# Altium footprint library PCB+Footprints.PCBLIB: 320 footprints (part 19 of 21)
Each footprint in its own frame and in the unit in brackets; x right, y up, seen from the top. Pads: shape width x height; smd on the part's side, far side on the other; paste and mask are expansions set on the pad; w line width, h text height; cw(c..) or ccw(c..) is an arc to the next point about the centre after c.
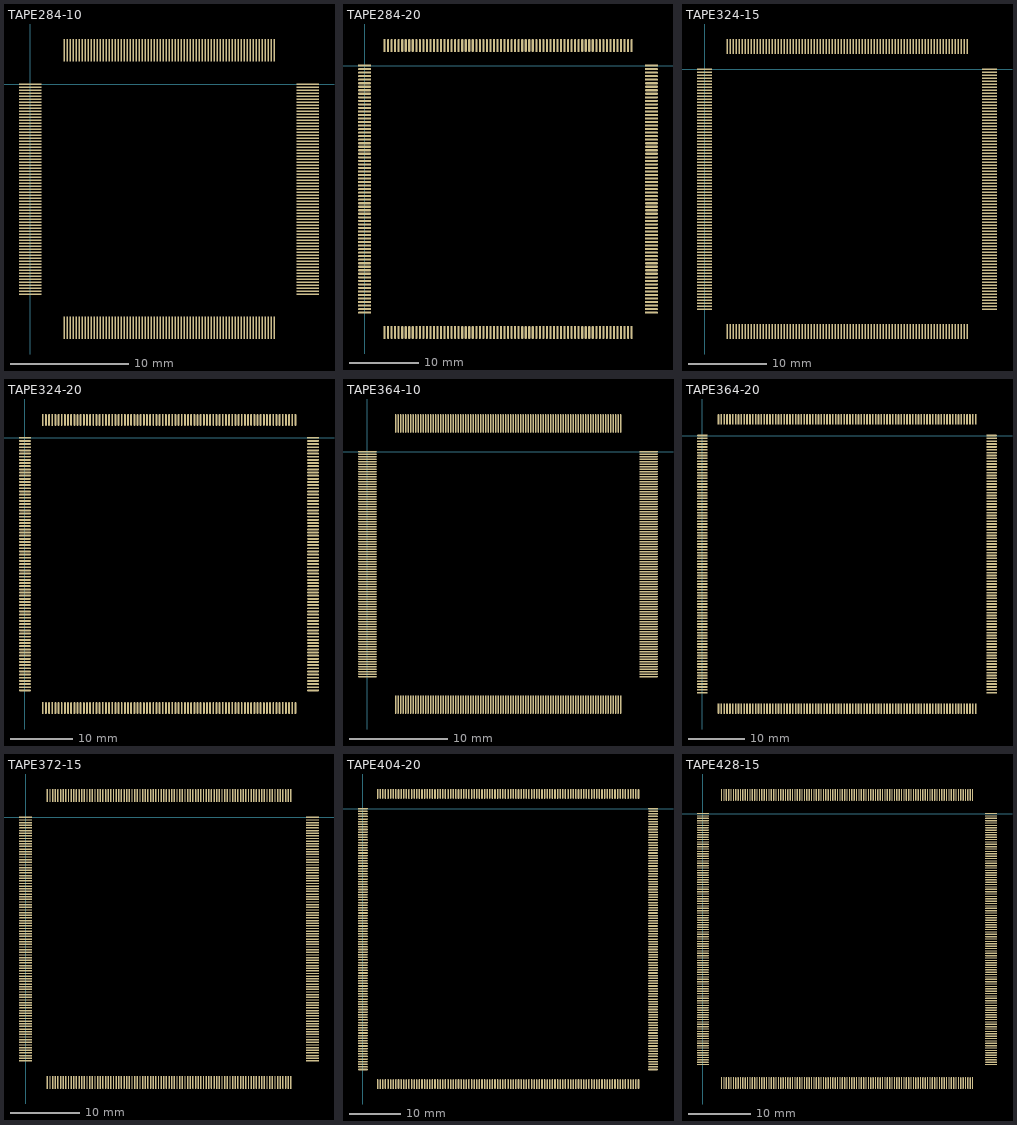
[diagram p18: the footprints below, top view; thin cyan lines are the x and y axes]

## TAPE284-10 [mil]
pads (284):
  oval 75x5 smd: 1(0,0) 2(0,-10) 3(0,-20) 4(0,-30) 5(0,-40) 6(0,-50) 7(0,-60) 8(0,-70) 9(0,-80) 10(0,-90) 11(0,-100) 12(0,-110) 13(0,-120) 14(0,-130) 15(0,-140) 16(0,-150) 17(0,-160) 18(0,-170) 19(0,-180) 20(0,-190) 21(0,-200) 22(0,-210) 23(0,-220) 24(0,-230) 25(0,-240) 26(0,-250) 27(0,-260) 28(0,-270) 29(0,-280) 30(0,-290) 31(0,-300) 32(0,-310) 33(0,-320) 34(0,-330) 35(0,-340) 36(0,-350) 37(0,-360) 38(0,-370) 39(0,-380) 40(0,-390) 41(0,-400) 42(0,-410) 43(0,-420) 44(0,-430) 45(0,-440) 46(0,-450) 47(0,-460) 48(0,-470) 49(0,-480) 50(0,-490) 51(0,-500) 52(0,-510) 53(0,-520) 54(0,-530) 55(0,-540) 56(0,-550) 57(0,-560) 58(0,-570) 59(0,-580) 60(0,-590) 61(0,-600) 62(0,-610) 63(0,-620) 64(0,-630) 65(0,-640) 66(0,-650) 67(0,-660) 68(0,-670) 69(0,-680) 70(0,-690) 71(0,-700) 143(925,-700) 144(925,-690) 145(925,-680) 146(925,-670) 147(925,-660) 148(925,-650) 149(925,-640) 150(925,-630) 151(925,-620) 152(925,-610) 153(925,-600) 154(925,-590) 155(925,-580) 156(925,-570) 157(925,-560) 158(925,-550) 159(925,-540) 160(925,-530) 161(925,-520) 162(925,-510) 163(925,-500) 164(925,-490) 165(925,-480) 166(925,-470) 167(925,-460) 168(925,-450) 169(925,-440) 170(925,-430) 171(925,-420) 172(925,-410) 173(925,-400) 174(925,-390) 175(925,-380) 176(925,-370) 177(925,-360) 178(925,-350) 179(925,-340) 180(925,-330) 181(925,-320) 182(925,-310) 183(925,-300) 184(925,-290) 185(925,-280) 186(925,-270) 187(925,-260) 188(925,-250) 189(925,-240) 190(925,-230) 191(925,-220) 192(925,-210) 193(925,-200) 194(925,-190) 195(925,-180) 196(925,-170) 197(925,-160) 198(925,-150) 199(925,-140) 200(925,-130) 201(925,-120) 202(925,-110) 203(925,-100) 204(925,-90) 205(925,-80) 206(925,-70) 207(925,-60) 208(925,-50) 209(925,-40) 210(925,-30) 211(925,-20) 212(925,-10) 213(925,0)
  oval 5x75 smd: 72(113,-812) 73(123,-812) 74(133,-812) 75(143,-812) 76(153,-812) 77(163,-812) 78(173,-812) 79(183,-812) 80(193,-812) 81(203,-812) 82(213,-812) 83(223,-812) 84(233,-812) 85(243,-812) 86(253,-812) 87(263,-812) 88(273,-812) 89(283,-812) 90(293,-812) 91(303,-812) 92(313,-812) 93(323,-812) 94(333,-812) 95(343,-812) 96(353,-812) 97(363,-812) 98(373,-812) 99(383,-812) 100(393,-812) 101(403,-812) 102(413,-812) 103(423,-812) 104(433,-812) 105(443,-812) 106(453,-812) 107(463,-812) 108(473,-812) 109(483,-812) 110(493,-812) 111(503,-812) 112(513,-812) 113(523,-812) 114(533,-812) 115(543,-812) 116(553,-812) 117(563,-812) 118(573,-812) 119(583,-812) 120(593,-812) 121(603,-812) 122(613,-812) 123(623,-812) 124(633,-812) 125(643,-812) 126(653,-812) 127(663,-812) 128(673,-812) 129(683,-812) 130(693,-812) 131(703,-812) 132(713,-812) 133(723,-812) 134(733,-812) 135(743,-812) 136(753,-812) 137(763,-812) 138(773,-812) 139(783,-812) 140(793,-812) 141(803,-812) 142(813,-812) 214(813,113) 215(803,113) 216(793,113) 217(783,113) 218(773,113) 219(763,113) 220(753,113) 221(743,113) 222(733,113) 223(723,113) 224(713,113) 225(703,113) 226(693,113) 227(683,113) 228(673,113) 229(663,113) 230(653,113) 231(643,113) 232(633,113) 233(623,113) 234(613,113) 235(603,113) 236(593,113) 237(583,113) 238(573,113) 239(563,113) 240(553,113) 241(543,113) 242(533,113) 243(523,113) 244(513,113) 245(503,113) 246(493,113) 247(483,113) 248(473,113) 249(463,113) 250(453,113) 251(443,113) 252(433,113) 253(423,113) 254(413,113) 255(403,113) 256(393,113) 257(383,113) 258(373,113) 259(363,113) 260(353,113) 261(343,113) 262(333,113) 263(323,113) 264(313,113) 265(303,113) 266(293,113) 267(283,113) 268(273,113) 269(263,113) 270(253,113) 271(243,113) 272(233,113) 273(223,113) 274(213,113) 275(203,113) 276(193,113) 277(183,113) 278(173,113) 279(163,113) 280(153,113) 281(143,113) 282(133,113) 283(123,113) 284(113,113)

## TAPE284-20 [mil]
pads (284):
  oval 75x12 smd: 1(0,0) 2(0,-20) 3(0,-40) 4(0,-60) 5(0,-80) 6(0,-100) 7(0,-120) 8(0,-140) 9(0,-160) 10(0,-180) 11(0,-200) 12(0,-220) 13(0,-240) 14(0,-260) 15(0,-280) 16(0,-300) 17(0,-320) 18(0,-340) 19(0,-360) 20(0,-380) 21(0,-400) 22(0,-420) 23(0,-440) 24(0,-460) 25(0,-480) 26(0,-500) 27(0,-520) 28(0,-540) 29(0,-560) 30(0,-580) 31(0,-600) 32(0,-620) 33(0,-640) 34(0,-660) 35(0,-680) 36(0,-700) 37(0,-720) 38(0,-740) 39(0,-760) 40(0,-780) 41(0,-800) 42(0,-820) 43(0,-840) 44(0,-860) 45(0,-880) 46(0,-900) 47(0,-920) 48(0,-940) 49(0,-960) 50(0,-980) 51(0,-1000) 52(0,-1020) 53(0,-1040) 54(0,-1060) 55(0,-1080) 56(0,-1100) 57(0,-1120) 58(0,-1140) 59(0,-1160) 60(0,-1180) 61(0,-1200) 62(0,-1220) 63(0,-1240) 64(0,-1260) 65(0,-1280) 66(0,-1300) 67(0,-1320) 68(0,-1340) 69(0,-1360) 70(0,-1380) 71(0,-1400) 143(1625,-1400) 144(1625,-1380) 145(1625,-1360) 146(1625,-1340) 147(1625,-1320) 148(1625,-1300) 149(1625,-1280) 150(1625,-1260) 151(1625,-1240) 152(1625,-1220) 153(1625,-1200) 154(1625,-1180) 155(1625,-1160) 156(1625,-1140) 157(1625,-1120) 158(1625,-1100) 159(1625,-1080) 160(1625,-1060) 161(1625,-1040) 162(1625,-1020) 163(1625,-1000) 164(1625,-980) 165(1625,-960) 166(1625,-940) 167(1625,-920) 168(1625,-900) 169(1625,-880) 170(1625,-860) 171(1625,-840) 172(1625,-820) 173(1625,-800) 174(1625,-780) 175(1625,-760) 176(1625,-740) 177(1625,-720) 178(1625,-700) 179(1625,-680) 180(1625,-660) 181(1625,-640) 182(1625,-620) 183(1625,-600) 184(1625,-580) 185(1625,-560) 186(1625,-540) 187(1625,-520) 188(1625,-500) 189(1625,-480) 190(1625,-460) 191(1625,-440) 192(1625,-420) 193(1625,-400) 194(1625,-380) 195(1625,-360) 196(1625,-340) 197(1625,-320) 198(1625,-300) 199(1625,-280) 200(1625,-260) 201(1625,-240) 202(1625,-220) 203(1625,-200) 204(1625,-180) 205(1625,-160) 206(1625,-140) 207(1625,-120) 208(1625,-100) 209(1625,-80) 210(1625,-60) 211(1625,-40) 212(1625,-20) 213(1625,0)
  oval 12x75 smd: 72(113,-1512) 73(133,-1512) 74(153,-1512) 75(173,-1512) 76(193,-1512) 77(213,-1512) 78(233,-1512) 79(253,-1512) 80(273,-1512) 81(293,-1512) 82(313,-1512) 83(333,-1512) 84(353,-1512) 85(373,-1512) 86(393,-1512) 87(413,-1512) 88(433,-1512) 89(453,-1512) 90(473,-1512) 91(493,-1512) 92(513,-1512) 93(533,-1512) 94(553,-1512) 95(573,-1512) 96(593,-1512) 97(613,-1512) 98(633,-1512) 99(653,-1512) 100(673,-1512) 101(693,-1512) 102(713,-1512) 103(733,-1512) 104(753,-1512) 105(773,-1512) 106(793,-1512) 107(813,-1512) 108(833,-1512) 109(853,-1512) 110(873,-1512) 111(893,-1512) 112(913,-1512) 113(933,-1512) 114(953,-1512) 115(973,-1512) 116(993,-1512) 117(1013,-1512) 118(1033,-1512) 119(1053,-1512) 120(1073,-1512) 121(1093,-1512) 122(1113,-1512) 123(1133,-1512) 124(1153,-1512) 125(1173,-1512) 126(1193,-1512) 127(1213,-1512) 128(1233,-1512) 129(1253,-1512) 130(1273,-1512) 131(1293,-1512) 132(1313,-1512) 133(1333,-1512) 134(1353,-1512) 135(1373,-1512) 136(1393,-1512) 137(1413,-1512) 138(1433,-1512) 139(1453,-1512) 140(1473,-1512) 141(1493,-1512) 142(1513,-1512) 214(1513,113) 215(1493,113) 216(1473,113) 217(1453,113) 218(1433,113) 219(1413,113) 220(1393,113) 221(1373,113) 222(1353,113) 223(1333,113) 224(1313,113) 225(1293,113) 226(1273,113) 227(1253,113) 228(1233,113) 229(1213,113) 230(1193,113) 231(1173,113) 232(1153,113) 233(1133,113) 234(1113,113) 235(1093,113) 236(1073,113) 237(1053,113) 238(1033,113) 239(1013,113) 240(993,113) 241(973,113) 242(953,113) 243(933,113) 244(913,113) 245(893,113) 246(873,113) 247(853,113) 248(833,113) 249(813,113) 250(793,113) 251(773,113) 252(753,113) 253(733,113) 254(713,113) 255(693,113) 256(673,113) 257(653,113) 258(633,113) 259(613,113) 260(593,113) 261(573,113) 262(553,113) 263(533,113) 264(513,113) 265(493,113) 266(473,113) 267(453,113) 268(433,113) 269(413,113) 270(393,113) 271(373,113) 272(353,113) 273(333,113) 274(313,113) 275(293,113) 276(273,113) 277(253,113) 278(233,113) 279(213,113) 280(193,113) 281(173,113) 282(153,113) 283(133,113) 284(113,113)

## TAPE324-15 [mil]
pads (324):
  oval 75x8 smd: 1(0,0) 2(0,-15) 3(0,-30) 4(0,-45) 5(0,-60) 6(0,-75) 7(0,-90) 8(0,-105) 9(0,-120) 10(0,-135) 11(0,-150) 12(0,-165) 13(0,-180) 14(0,-195) 15(0,-210) 16(0,-225) 17(0,-240) 18(0,-255) 19(0,-270) 20(0,-285) 21(0,-300) 22(0,-315) 23(0,-330) 24(0,-345) 25(0,-360) 26(0,-375) 27(0,-390) 28(0,-405) 29(0,-420) 30(0,-435) 31(0,-450) 32(0,-465) 33(0,-480) 34(0,-495) 35(0,-510) 36(0,-525) 37(0,-540) 38(0,-555) 39(0,-570) 40(0,-585) 41(0,-600) 42(0,-615) 43(0,-630) 44(0,-645) 45(0,-660) 46(0,-675) 47(0,-690) 48(0,-705) 49(0,-720) 50(0,-735) 51(0,-750) 52(0,-765) 53(0,-780) 54(0,-795) 55(0,-810) 56(0,-825) 57(0,-840) 58(0,-855) 59(0,-870) 60(0,-885) 61(0,-900) 62(0,-915) 63(0,-930) 64(0,-945) 65(0,-960) 66(0,-975) 67(0,-990) 68(0,-1005) 69(0,-1020) 70(0,-1035) 71(0,-1050) 72(0,-1065) 73(0,-1080) 74(0,-1095) 75(0,-1110) 76(0,-1125) 77(0,-1140) 78(0,-1155) 79(0,-1170) 80(0,-1185) 81(0,-1200) 163(1425,-1200) 164(1425,-1185) 165(1425,-1170) 166(1425,-1155) 167(1425,-1140) 168(1425,-1125) 169(1425,-1110) 170(1425,-1095) 171(1425,-1080) 172(1425,-1065) 173(1425,-1050) 174(1425,-1035) 175(1425,-1020) 176(1425,-1005) 177(1425,-990) 178(1425,-975) 179(1425,-960) 180(1425,-945) 181(1425,-930) 182(1425,-915) 183(1425,-900) 184(1425,-885) 185(1425,-870) 186(1425,-855) 187(1425,-840) 188(1425,-825) 189(1425,-810) 190(1425,-795) 191(1425,-780) 192(1425,-765) 193(1425,-750) 194(1425,-735) 195(1425,-720) 196(1425,-705) 197(1425,-690) 198(1425,-675) 199(1425,-660) 200(1425,-645) 201(1425,-630) 202(1425,-615) 203(1425,-600) 204(1425,-585) 205(1425,-570) 206(1425,-555) 207(1425,-540) 208(1425,-525) 209(1425,-510) 210(1425,-495) 211(1425,-480) 212(1425,-465) 213(1425,-450) 214(1425,-435) 215(1425,-420) 216(1425,-405) 217(1425,-390) 218(1425,-375) 219(1425,-360) 220(1425,-345) 221(1425,-330) 222(1425,-315) 223(1425,-300) 224(1425,-285) 225(1425,-270) 226(1425,-255) 227(1425,-240) 228(1425,-225) 229(1425,-210) 230(1425,-195) 231(1425,-180) 232(1425,-165) 233(1425,-150) 234(1425,-135) 235(1425,-120) 236(1425,-105) 237(1425,-90) 238(1425,-75) 239(1425,-60) 240(1425,-45) 241(1425,-30) 242(1425,-15) 243(1425,0)
  oval 8x75 smd: 82(113,-1312) 83(128,-1312) 84(143,-1312) 85(158,-1312) 86(173,-1312) 87(188,-1312) 88(203,-1312) 89(218,-1312) 90(233,-1312) 91(248,-1312) 92(263,-1312) 93(278,-1312) 94(293,-1312) 95(308,-1312) 96(323,-1312) 97(338,-1312) 98(353,-1312) 99(368,-1312) 100(383,-1312) 101(398,-1312) 102(413,-1312) 103(428,-1312) 104(443,-1312) 105(458,-1312) 106(473,-1312) 107(488,-1312) 108(503,-1312) 109(518,-1312) 110(533,-1312) 111(548,-1312) 112(563,-1312) 113(578,-1312) 114(593,-1312) 115(608,-1312) 116(623,-1312) 117(638,-1312) 118(653,-1312) 119(668,-1312) 120(683,-1312) 121(698,-1312) 122(713,-1312) 123(728,-1312) 124(743,-1312) 125(758,-1312) 126(773,-1312) 127(788,-1312) 128(803,-1312) 129(818,-1312) 130(833,-1312) 131(848,-1312) 132(863,-1312) 133(878,-1312) 134(893,-1312) 135(908,-1312) 136(923,-1312) 137(938,-1312) 138(953,-1312) 139(968,-1312) 140(983,-1312) 141(998,-1312) 142(1013,-1312) 143(1028,-1312) 144(1043,-1312) 145(1058,-1312) 146(1073,-1312) 147(1088,-1312) 148(1103,-1312) 149(1118,-1312) 150(1133,-1312) 151(1148,-1312) 152(1163,-1312) 153(1178,-1312) 154(1193,-1312) 155(1208,-1312) 156(1223,-1312) 157(1238,-1312) 158(1253,-1312) 159(1268,-1312) 160(1283,-1312) 161(1298,-1312) 162(1313,-1312) 244(1313,113) 245(1298,113) 246(1283,113) 247(1268,113) 248(1253,113) 249(1238,113) 250(1223,113) 251(1208,113) 252(1193,113) 253(1178,113) 254(1163,113) 255(1148,113) 256(1133,113) 257(1118,113) 258(1103,113) 259(1088,113) 260(1073,113) 261(1058,113) 262(1043,113) 263(1028,113) 264(1013,113) 265(998,113) 266(983,113) 267(968,113) 268(953,113) 269(938,113) 270(923,113) 271(908,113) 272(893,113) 273(878,113) 274(863,113) 275(848,113) 276(833,113) 277(818,113) 278(803,113) 279(788,113) 280(773,113) 281(758,113) 282(743,113) 283(728,113) 284(713,113) 285(698,113) 286(683,113) 287(668,113) 288(653,113) 289(638,113) 290(623,113) 291(608,113) 292(593,113) 293(578,113) 294(563,113) 295(548,113) 296(533,113) 297(518,113) 298(503,113) 299(488,113) 300(473,113) 301(458,113) 302(443,113) 303(428,113) 304(413,113) 305(398,113) 306(383,113) 307(368,113) 308(353,113) 309(338,113) 310(323,113) 311(308,113) 312(293,113) 313(278,113) 314(263,113) 315(248,113) 316(233,113) 317(218,113) 318(203,113) 319(188,113) 320(173,113) 321(158,113) 322(143,113) 323(128,113) 324(113,113)

## TAPE324-20 [mil]
pads (324):
  oval 75x12 smd: 1(0,0) 2(0,-20) 3(0,-40) 4(0,-60) 5(0,-80) 6(0,-100) 7(0,-120) 8(0,-140) 9(0,-160) 10(0,-180) 11(0,-200) 12(0,-220) 13(0,-240) 14(0,-260) 15(0,-280) 16(0,-300) 17(0,-320) 18(0,-340) 19(0,-360) 20(0,-380) 21(0,-400) 22(0,-420) 23(0,-440) 24(0,-460) 25(0,-480) 26(0,-500) 27(0,-520) 28(0,-540) 29(0,-560) 30(0,-580) 31(0,-600) 32(0,-620) 33(0,-640) 34(0,-660) 35(0,-680) 36(0,-700) 37(0,-720) 38(0,-740) 39(0,-760) 40(0,-780) 41(0,-800) 42(0,-820) 43(0,-840) 44(0,-860) 45(0,-880) 46(0,-900) 47(0,-920) 48(0,-940) 49(0,-960) 50(0,-980) 51(0,-1000) 52(0,-1020) 53(0,-1040) 54(0,-1060) 55(0,-1080) 56(0,-1100) 57(0,-1120) 58(0,-1140) 59(0,-1160) 60(0,-1180) 61(0,-1200) 62(0,-1220) 63(0,-1240) 64(0,-1260) 65(0,-1280) 66(0,-1300) 67(0,-1320) 68(0,-1340) 69(0,-1360) 70(0,-1380) 71(0,-1400) 72(0,-1420) 73(0,-1440) 74(0,-1460) 75(0,-1480) 76(0,-1500) 77(0,-1520) 78(0,-1540) 79(0,-1560) 80(0,-1580) 81(0,-1600) 163(1825,-1600) 164(1825,-1580) 165(1825,-1560) 166(1825,-1540) 167(1825,-1520) 168(1825,-1500) 169(1825,-1480) 170(1825,-1460) 171(1825,-1440) 172(1825,-1420) 173(1825,-1400) 174(1825,-1380) 175(1825,-1360) 176(1825,-1340) 177(1825,-1320) 178(1825,-1300) 179(1825,-1280) 180(1825,-1260) 181(1825,-1240) 182(1825,-1220) 183(1825,-1200) 184(1825,-1180) 185(1825,-1160) 186(1825,-1140) 187(1825,-1120) 188(1825,-1100) 189(1825,-1080) 190(1825,-1060) 191(1825,-1040) 192(1825,-1020) 193(1825,-1000) 194(1825,-980) 195(1825,-960) 196(1825,-940) 197(1825,-920) 198(1825,-900) 199(1825,-880) 200(1825,-860) 201(1825,-840) 202(1825,-820) 203(1825,-800) 204(1825,-780) 205(1825,-760) 206(1825,-740) 207(1825,-720) 208(1825,-700) 209(1825,-680) 210(1825,-660) 211(1825,-640) 212(1825,-620) 213(1825,-600) 214(1825,-580) 215(1825,-560) 216(1825,-540) 217(1825,-520) 218(1825,-500) 219(1825,-480) 220(1825,-460) 221(1825,-440) 222(1825,-420) 223(1825,-400) 224(1825,-380) 225(1825,-360) 226(1825,-340) 227(1825,-320) 228(1825,-300) 229(1825,-280) 230(1825,-260) 231(1825,-240) 232(1825,-220) 233(1825,-200) 234(1825,-180) 235(1825,-160) 236(1825,-140) 237(1825,-120) 238(1825,-100) 239(1825,-80) 240(1825,-60) 241(1825,-40) 242(1825,-20) 243(1825,0)
  oval 12x75 smd: 82(113,-1712) 83(133,-1712) 84(153,-1712) 85(173,-1712) 86(193,-1712) 87(213,-1712) 88(233,-1712) 89(253,-1712) 90(273,-1712) 91(293,-1712) 92(313,-1712) 93(333,-1712) 94(353,-1712) 95(373,-1712) 96(393,-1712) 97(413,-1712) 98(433,-1712) 99(453,-1712) 100(473,-1712) 101(493,-1712) 102(513,-1712) 103(533,-1712) 104(553,-1712) 105(573,-1712) 106(593,-1712) 107(613,-1712) 108(633,-1712) 109(653,-1712) 110(673,-1712) 111(693,-1712) 112(713,-1712) 113(733,-1712) 114(753,-1712) 115(773,-1712) 116(793,-1712) 117(813,-1712) 118(833,-1712) 119(853,-1712) 120(873,-1712) 121(893,-1712) 122(913,-1712) 123(933,-1712) 124(953,-1712) 125(973,-1712) 126(993,-1712) 127(1013,-1712) 128(1033,-1712) 129(1053,-1712) 130(1073,-1712) 131(1093,-1712) 132(1113,-1712) 133(1133,-1712) 134(1153,-1712) 135(1173,-1712) 136(1193,-1712) 137(1213,-1712) 138(1233,-1712) 139(1253,-1712) 140(1273,-1712) 141(1293,-1712) 142(1313,-1712) 143(1333,-1712) 144(1353,-1712) 145(1373,-1712) 146(1393,-1712) 147(1413,-1712) 148(1433,-1712) 149(1453,-1712) 150(1473,-1712) 151(1493,-1712) 152(1513,-1712) 153(1533,-1712) 154(1553,-1712) 155(1573,-1712) 156(1593,-1712) 157(1613,-1712) 158(1633,-1712) 159(1653,-1712) 160(1673,-1712) 161(1693,-1712) 162(1713,-1712) 244(1713,113) 245(1693,113) 246(1673,113) 247(1653,113) 248(1633,113) 249(1613,113) 250(1593,113) 251(1573,113) 252(1553,113) 253(1533,113) 254(1513,113) 255(1493,113) 256(1473,113) 257(1453,113) 258(1433,113) 259(1413,113) 260(1393,113) 261(1373,113) 262(1353,113) 263(1333,113) 264(1313,113) 265(1293,113) 266(1273,113) 267(1253,113) 268(1233,113) 269(1213,113) 270(1193,113) 271(1173,113) 272(1153,113) 273(1133,113) 274(1113,113) 275(1093,113) 276(1073,113) 277(1053,113) 278(1033,113) 279(1013,113) 280(993,113) 281(973,113) 282(953,113) 283(933,113) 284(913,113) 285(893,113) 286(873,113) 287(853,113) 288(833,113) 289(813,113) 290(793,113) 291(773,113) 292(753,113) 293(733,113) 294(713,113) 295(693,113) 296(673,113) 297(653,113) 298(633,113) 299(613,113) 300(593,113) 301(573,113) 302(553,113) 303(533,113) 304(513,113) 305(493,113) 306(473,113) 307(453,113) 308(433,113) 309(413,113) 310(393,113) 311(373,113) 312(353,113) 313(333,113) 314(313,113) 315(293,113) 316(273,113) 317(253,113) 318(233,113) 319(213,113) 320(193,113) 321(173,113) 322(153,113) 323(133,113) 324(113,113)

## TAPE364-10 [mil]
pads (364):
  oval 75x5 smd: 1(0,0) 2(0,-10) 3(0,-20) 4(0,-30) 5(0,-40) 6(0,-50) 7(0,-60) 8(0,-70) 9(0,-80) 10(0,-90) 11(0,-100) 12(0,-110) 13(0,-120) 14(0,-130) 15(0,-140) 16(0,-150) 17(0,-160) 18(0,-170) 19(0,-180) 20(0,-190) 21(0,-200) 22(0,-210) 23(0,-220) 24(0,-230) 25(0,-240) 26(0,-250) 27(0,-260) 28(0,-270) 29(0,-280) 30(0,-290) 31(0,-300) 32(0,-310) 33(0,-320) 34(0,-330) 35(0,-340) 36(0,-350) 37(0,-360) 38(0,-370) 39(0,-380) 40(0,-390) 41(0,-400) 42(0,-410) 43(0,-420) 44(0,-430) 45(0,-440) 46(0,-450) 47(0,-460) 48(0,-470) 49(0,-480) 50(0,-490) 51(0,-500) 52(0,-510) 53(0,-520) 54(0,-530) 55(0,-540) 56(0,-550) 57(0,-560) 58(0,-570) 59(0,-580) 60(0,-590) 61(0,-600) 62(0,-610) 63(0,-620) 64(0,-630) 65(0,-640) 66(0,-650) 67(0,-660) 68(0,-670) 69(0,-680) 70(0,-690) 71(0,-700) 72(0,-710) 73(0,-720) 74(0,-730) 75(0,-740) 76(0,-750) 77(0,-760) 78(0,-770) 79(0,-780) 80(0,-790) 81(0,-800) 82(0,-810) 83(0,-820) 84(0,-830) 85(0,-840) 86(0,-850) 87(0,-860) 88(0,-870) 89(0,-880) 90(0,-890) 91(0,-900) 183(1125,-900) 184(1125,-890) 185(1125,-880) 186(1125,-870) 187(1125,-860) 188(1125,-850) 189(1125,-840) 190(1125,-830) 191(1125,-820) 192(1125,-810) 193(1125,-800) 194(1125,-790) 195(1125,-780) 196(1125,-770) 197(1125,-760) 198(1125,-750) 199(1125,-740) 200(1125,-730) 201(1125,-720) 202(1125,-710) 203(1125,-700) 204(1125,-690) 205(1125,-680) 206(1125,-670) 207(1125,-660) 208(1125,-650) 209(1125,-640) 210(1125,-630) 211(1125,-620) 212(1125,-610) 213(1125,-600) 214(1125,-590) 215(1125,-580) 216(1125,-570) 217(1125,-560) 218(1125,-550) 219(1125,-540) 220(1125,-530) 221(1125,-520) 222(1125,-510) 223(1125,-500) 224(1125,-490) 225(1125,-480) 226(1125,-470) 227(1125,-460) 228(1125,-450) 229(1125,-440) 230(1125,-430) 231(1125,-420) 232(1125,-410) 233(1125,-400) 234(1125,-390) 235(1125,-380) 236(1125,-370) 237(1125,-360) 238(1125,-350) 239(1125,-340) 240(1125,-330) 241(1125,-320) 242(1125,-310) 243(1125,-300) 244(1125,-290) 245(1125,-280) 246(1125,-270) 247(1125,-260) 248(1125,-250) 249(1125,-240) 250(1125,-230) 251(1125,-220) 252(1125,-210) 253(1125,-200) 254(1125,-190) 255(1125,-180) 256(1125,-170) 257(1125,-160) 258(1125,-150) 259(1125,-140) 260(1125,-130) 261(1125,-120) 262(1125,-110) 263(1125,-100) 264(1125,-90) 265(1125,-80) 266(1125,-70) 267(1125,-60) 268(1125,-50) 269(1125,-40) 270(1125,-30) 271(1125,-20) 272(1125,-10) 273(1125,0)
  oval 5x75 smd: 92(113,-1012) 93(123,-1012) 94(133,-1012) 95(143,-1012) 96(153,-1012) 97(163,-1012) 98(173,-1012) 99(183,-1012) 100(193,-1012) 101(203,-1012) 102(213,-1012) 103(223,-1012) 104(233,-1012) 105(243,-1012) 106(253,-1012) 107(263,-1012) 108(273,-1012) 109(283,-1012) 110(293,-1012) 111(303,-1012) 112(313,-1012) 113(323,-1012) 114(333,-1012) 115(343,-1012) 116(353,-1012) 117(363,-1012) 118(373,-1012) 119(383,-1012) 120(393,-1012) 121(403,-1012) 122(413,-1012) 123(423,-1012) 124(433,-1012) 125(443,-1012) 126(453,-1012) 127(463,-1012) 128(473,-1012) 129(483,-1012) 130(493,-1012) 131(503,-1012) 132(513,-1012) 133(523,-1012) 134(533,-1012) 135(543,-1012) 136(553,-1012) 137(563,-1012) 138(573,-1012) 139(583,-1012) 140(593,-1012) 141(603,-1012) 142(613,-1012) 143(623,-1012) 144(633,-1012) 145(643,-1012) 146(653,-1012) 147(663,-1012) 148(673,-1012) 149(683,-1012) 150(693,-1012) 151(703,-1012) 152(713,-1012) 153(723,-1012) 154(733,-1012) 155(743,-1012) 156(753,-1012) 157(763,-1012) 158(773,-1012) 159(783,-1012) 160(793,-1012) 161(803,-1012) 162(813,-1012) 163(823,-1012) 164(833,-1012) 165(843,-1012) 166(853,-1012) 167(863,-1012) 168(873,-1012) 169(883,-1012) 170(893,-1012) 171(903,-1012) 172(913,-1012) 173(923,-1012) 174(933,-1012) 175(943,-1012) 176(953,-1012) 177(963,-1012) 178(973,-1012) 179(983,-1012) 180(993,-1012) 181(1003,-1012) 182(1013,-1012) 274(1013,113) 275(1003,113) 276(993,113) 277(983,113) 278(973,113) 279(963,113) 280(953,113) 281(943,113) 282(933,113) 283(923,113) 284(913,113) 285(903,113) 286(893,113) 287(883,113) 288(873,113) 289(863,113) 290(853,113) 291(843,113) 292(833,113) 293(823,113) 294(813,113) 295(803,113) 296(793,113) 297(783,113) 298(773,113) 299(763,113) 300(753,113) 301(743,113) 302(733,113) 303(723,113) 304(713,113) 305(703,113) 306(693,113) 307(683,113) 308(673,113) 309(663,113) 310(653,113) 311(643,113) 312(633,113) 313(623,113) 314(613,113) 315(603,113) 316(593,113) 317(583,113) 318(573,113) 319(563,113) 320(553,113) 321(543,113) 322(533,113) 323(523,113) 324(513,113) 325(503,113) 326(493,113) 327(483,113) 328(473,113) 329(463,113) 330(453,113) 331(443,113) 332(433,113) 333(423,113) 334(413,113) 335(403,113) 336(393,113) 337(383,113) 338(373,113) 339(363,113) 340(353,113) 341(343,113) 342(333,113) 343(323,113) 344(313,113) 345(303,113) 346(293,113) 347(283,113) 348(273,113) 349(263,113) 350(253,113) 351(243,113) 352(233,113) 353(223,113) 354(213,113) 355(203,113) 356(193,113) 357(183,113) 358(173,113) 359(163,113) 360(153,113) 361(143,113) 362(133,113) 363(123,113) 364(113,113)

## TAPE364-20 [mil]
pads (364):
  oval 75x12 smd: 1(0,0) 2(0,-20) 3(0,-40) 4(0,-60) 5(0,-80) 6(0,-100) 7(0,-120) 8(0,-140) 9(0,-160) 10(0,-180) 11(0,-200) 12(0,-220) 13(0,-240) 14(0,-260) 15(0,-280) 16(0,-300) 17(0,-320) 18(0,-340) 19(0,-360) 20(0,-380) 21(0,-400) 22(0,-420) 23(0,-440) 24(0,-460) 25(0,-480) 26(0,-500) 27(0,-520) 28(0,-540) 29(0,-560) 30(0,-580) 31(0,-600) 32(0,-620) 33(0,-640) 34(0,-660) 35(0,-680) 36(0,-700) 37(0,-720) 38(0,-740) 39(0,-760) 40(0,-780) 41(0,-800) 42(0,-820) 43(0,-840) 44(0,-860) 45(0,-880) 46(0,-900) 47(0,-920) 48(0,-940) 49(0,-960) 50(0,-980) 51(0,-1000) 52(0,-1020) 53(0,-1040) 54(0,-1060) 55(0,-1080) 56(0,-1100) 57(0,-1120) 58(0,-1140) 59(0,-1160) 60(0,-1180) 61(0,-1200) 62(0,-1220) 63(0,-1240) 64(0,-1260) 65(0,-1280) 66(0,-1300) 67(0,-1320) 68(0,-1340) 69(0,-1360) 70(0,-1380) 71(0,-1400) 72(0,-1420) 73(0,-1440) 74(0,-1460) 75(0,-1480) 76(0,-1500) 77(0,-1520) 78(0,-1540) 79(0,-1560) 80(0,-1580) 81(0,-1600) 82(0,-1620) 83(0,-1640) 84(0,-1660) 85(0,-1680) 86(0,-1700) 87(0,-1720) 88(0,-1740) 89(0,-1760) 90(0,-1780) 91(0,-1800) 183(2025,-1800) 184(2025,-1780) 185(2025,-1760) 186(2025,-1740) 187(2025,-1720) 188(2025,-1700) 189(2025,-1680) 190(2025,-1660) 191(2025,-1640) 192(2025,-1620) 193(2025,-1600) 194(2025,-1580) 195(2025,-1560) 196(2025,-1540) 197(2025,-1520) 198(2025,-1500) 199(2025,-1480) 200(2025,-1460) 201(2025,-1440) 202(2025,-1420) 203(2025,-1400) 204(2025,-1380) 205(2025,-1360) 206(2025,-1340) 207(2025,-1320) 208(2025,-1300) 209(2025,-1280) 210(2025,-1260) 211(2025,-1240) 212(2025,-1220) 213(2025,-1200) 214(2025,-1180) 215(2025,-1160) 216(2025,-1140) 217(2025,-1120) 218(2025,-1100) 219(2025,-1080) 220(2025,-1060) 221(2025,-1040) 222(2025,-1020) 223(2025,-1000) 224(2025,-980) 225(2025,-960) 226(2025,-940) 227(2025,-920) 228(2025,-900) 229(2025,-880) 230(2025,-860) 231(2025,-840) 232(2025,-820) 233(2025,-800) 234(2025,-780) 235(2025,-760) 236(2025,-740) 237(2025,-720) 238(2025,-700) 239(2025,-680) 240(2025,-660) 241(2025,-640) 242(2025,-620) 243(2025,-600) 244(2025,-580) 245(2025,-560) 246(2025,-540) 247(2025,-520) 248(2025,-500) 249(2025,-480) 250(2025,-460) 251(2025,-440) 252(2025,-420) 253(2025,-400) 254(2025,-380) 255(2025,-360) 256(2025,-340) 257(2025,-320) 258(2025,-300) 259(2025,-280) 260(2025,-260) 261(2025,-240) 262(2025,-220) 263(2025,-200) 264(2025,-180) 265(2025,-160) 266(2025,-140) 267(2025,-120) 268(2025,-100) 269(2025,-80) 270(2025,-60) 271(2025,-40) 272(2025,-20) 273(2025,0)
  oval 12x75 smd: 92(113,-1912) 93(133,-1912) 94(153,-1912) 95(173,-1912) 96(193,-1912) 97(213,-1912) 98(233,-1912) 99(253,-1912) 100(273,-1912) 101(293,-1912) 102(313,-1912) 103(333,-1912) 104(353,-1912) 105(373,-1912) 106(393,-1912) 107(413,-1912) 108(433,-1912) 109(453,-1912) 110(473,-1912) 111(493,-1912) 112(513,-1912) 113(533,-1912) 114(553,-1912) 115(573,-1912) 116(593,-1912) 117(613,-1912) 118(633,-1912) 119(653,-1912) 120(673,-1912) 121(693,-1912) 122(713,-1912) 123(733,-1912) 124(753,-1912) 125(773,-1912) 126(793,-1912) 127(813,-1912) 128(833,-1912) 129(853,-1912) 130(873,-1912) 131(893,-1912) 132(913,-1912) 133(933,-1912) 134(953,-1912) 135(973,-1912) 136(993,-1912) 137(1013,-1912) 138(1033,-1912) 139(1053,-1912) 140(1073,-1912) 141(1093,-1912) 142(1113,-1912) 143(1133,-1912) 144(1153,-1912) 145(1173,-1912) 146(1193,-1912) 147(1213,-1912) 148(1233,-1912) 149(1253,-1912) 150(1273,-1912) 151(1293,-1912) 152(1313,-1912) 153(1333,-1912) 154(1353,-1912) 155(1373,-1912) 156(1393,-1912) 157(1413,-1912) 158(1433,-1912) 159(1453,-1912) 160(1473,-1912) 161(1493,-1912) 162(1513,-1912) 163(1533,-1912) 164(1553,-1912) 165(1573,-1912) 166(1593,-1912) 167(1613,-1912) 168(1633,-1912) 169(1653,-1912) 170(1673,-1912) 171(1693,-1912) 172(1713,-1912) 173(1733,-1912) 174(1753,-1912) 175(1773,-1912) 176(1793,-1912) 177(1813,-1912) 178(1833,-1912) 179(1853,-1912) 180(1873,-1912) 181(1893,-1912) 182(1913,-1912) 274(1913,113) 275(1893,113) 276(1873,113) 277(1853,113) 278(1833,113) 279(1813,113) 280(1793,113) 281(1773,113) 282(1753,113) 283(1733,113) 284(1713,113) 285(1693,113) 286(1673,113) 287(1653,113) 288(1633,113) 289(1613,113) 290(1593,113) 291(1573,113) 292(1553,113) 293(1533,113) 294(1513,113) 295(1493,113) 296(1473,113) 297(1453,113) 298(1433,113) 299(1413,113) 300(1393,113) 301(1373,113) 302(1353,113) 303(1333,113) 304(1313,113) 305(1293,113) 306(1273,113) 307(1253,113) 308(1233,113) 309(1213,113) 310(1193,113) 311(1173,113) 312(1153,113) 313(1133,113) 314(1113,113) 315(1093,113) 316(1073,113) 317(1053,113) 318(1033,113) 319(1013,113) 320(993,113) 321(973,113) 322(953,113) 323(933,113) 324(913,113) 325(893,113) 326(873,113) 327(853,113) 328(833,113) 329(813,113) 330(793,113) 331(773,113) 332(753,113) 333(733,113) 334(713,113) 335(693,113) 336(673,113) 337(653,113) 338(633,113) 339(613,113) 340(593,113) 341(573,113) 342(553,113) 343(533,113) 344(513,113) 345(493,113) 346(473,113) 347(453,113) 348(433,113) 349(413,113) 350(393,113) 351(373,113) 352(353,113) 353(333,113) 354(313,113) 355(293,113) 356(273,113) 357(253,113) 358(233,113) 359(213,113) 360(193,113) 361(173,113) 362(153,113) 363(133,113) 364(113,113)

## TAPE372-15 [mil]
pads (372):
  oval 75x8 smd: 1(0,0) 2(0,-15) 3(0,-30) 4(0,-45) 5(0,-60) 6(0,-75) 7(0,-90) 8(0,-105) 9(0,-120) 10(0,-135) 11(0,-150) 12(0,-165) 13(0,-180) 14(0,-195) 15(0,-210) 16(0,-225) 17(0,-240) 18(0,-255) 19(0,-270) 20(0,-285) 21(0,-300) 22(0,-315) 23(0,-330) 24(0,-345) 25(0,-360) 26(0,-375) 27(0,-390) 28(0,-405) 29(0,-420) 30(0,-435) 31(0,-450) 32(0,-465) 33(0,-480) 34(0,-495) 35(0,-510) 36(0,-525) 37(0,-540) 38(0,-555) 39(0,-570) 40(0,-585) 41(0,-600) 42(0,-615) 43(0,-630) 44(0,-645) 45(0,-660) 46(0,-675) 47(0,-690) 48(0,-705) 49(0,-720) 50(0,-735) 51(0,-750) 52(0,-765) 53(0,-780) 54(0,-795) 55(0,-810) 56(0,-825) 57(0,-840) 58(0,-855) 59(0,-870) 60(0,-885) 61(0,-900) 62(0,-915) 63(0,-930) 64(0,-945) 65(0,-960) 66(0,-975) 67(0,-990) 68(0,-1005) 69(0,-1020) 70(0,-1035) 71(0,-1050) 72(0,-1065) 73(0,-1080) 74(0,-1095) 75(0,-1110) 76(0,-1125) 77(0,-1140) 78(0,-1155) 79(0,-1170) 80(0,-1185) 81(0,-1200) 82(0,-1215) 83(0,-1230) 84(0,-1245) 85(0,-1260) 86(0,-1275) 87(0,-1290) 88(0,-1305) 89(0,-1320) 90(0,-1335) 91(0,-1350) 92(0,-1365) 93(0,-1380) 187(1625,-1380) 188(1625,-1365) 189(1625,-1350) 190(1625,-1335) 191(1625,-1320) 192(1625,-1305) 193(1625,-1290) 194(1625,-1275) 195(1625,-1260) 196(1625,-1245) 197(1625,-1230) 198(1625,-1215) 199(1625,-1200) 200(1625,-1185) 201(1625,-1170) 202(1625,-1155) 203(1625,-1140) 204(1625,-1125) 205(1625,-1110) 206(1625,-1095) 207(1625,-1080) 208(1625,-1065) 209(1625,-1050) 210(1625,-1035) 211(1625,-1020) 212(1625,-1005) 213(1625,-990) 214(1625,-975) 215(1625,-960) 216(1625,-945) 217(1625,-930) 218(1625,-915) 219(1625,-900) 220(1625,-885) 221(1625,-870) 222(1625,-855) 223(1625,-840) 224(1625,-825) 225(1625,-810) 226(1625,-795) 227(1625,-780) 228(1625,-765) 229(1625,-750) 230(1625,-735) 231(1625,-720) 232(1625,-705) 233(1625,-690) 234(1625,-675) 235(1625,-660) 236(1625,-645) 237(1625,-630) 238(1625,-615) 239(1625,-600) 240(1625,-585) 241(1625,-570) 242(1625,-555) 243(1625,-540) 244(1625,-525) 245(1625,-510) 246(1625,-495) 247(1625,-480) 248(1625,-465) 249(1625,-450) 250(1625,-435) 251(1625,-420) 252(1625,-405) 253(1625,-390) 254(1625,-375) 255(1625,-360) 256(1625,-345) 257(1625,-330) 258(1625,-315) 259(1625,-300) 260(1625,-285) 261(1625,-270) 262(1625,-255) 263(1625,-240) 264(1625,-225) 265(1625,-210) 266(1625,-195) 267(1625,-180) 268(1625,-165) 269(1625,-150) 270(1625,-135) 271(1625,-120) 272(1625,-105) 273(1625,-90) 274(1625,-75) 275(1625,-60) 276(1625,-45) 277(1625,-30) 278(1625,-15) 279(1625,0)
  oval 8x75 smd: 94(123,-1502) 95(138,-1502) 96(153,-1502) 97(168,-1502) 98(183,-1502) 99(198,-1502) 100(213,-1502) 101(228,-1502) 102(243,-1502) 103(258,-1502) 104(273,-1502) 105(288,-1502) 106(303,-1502) 107(318,-1502) 108(333,-1502) 109(348,-1502) 110(363,-1502) 111(378,-1502) 112(393,-1502) 113(408,-1502) 114(423,-1502) 115(438,-1502) 116(453,-1502) 117(468,-1502) 118(483,-1502) 119(498,-1502) 120(513,-1502) 121(528,-1502) 122(543,-1502) 123(558,-1502) 124(573,-1502) 125(588,-1502) 126(603,-1502) 127(618,-1502) 128(633,-1502) 129(648,-1502) 130(663,-1502) 131(678,-1502) 132(693,-1502) 133(708,-1502) 134(723,-1502) 135(738,-1502) 136(753,-1502) 137(768,-1502) 138(783,-1502) 139(798,-1502) 140(813,-1502) 141(828,-1502) 142(843,-1502) 143(858,-1502) 144(873,-1502) 145(888,-1502) 146(903,-1502) 147(918,-1502) 148(933,-1502) 149(948,-1502) 150(963,-1502) 151(978,-1502) 152(993,-1502) 153(1008,-1502) 154(1023,-1502) 155(1038,-1502) 156(1053,-1502) 157(1068,-1502) 158(1083,-1502) 159(1098,-1502) 160(1113,-1502) 161(1128,-1502) 162(1143,-1502) 163(1158,-1502) 164(1173,-1502) 165(1188,-1502) 166(1203,-1502) 167(1218,-1502) 168(1233,-1502) 169(1248,-1502) 170(1263,-1502) 171(1278,-1502) 172(1293,-1502) 173(1308,-1502) 174(1323,-1502) 175(1338,-1502) 176(1353,-1502) 177(1368,-1502) 178(1383,-1502) 179(1398,-1502) 180(1413,-1502) 181(1428,-1502) 182(1443,-1502) 183(1458,-1502) 184(1473,-1502) 185(1488,-1502) 186(1503,-1502) 280(1503,123) 281(1488,123) 282(1473,123) 283(1458,123) 284(1443,123) 285(1428,123) 286(1413,123) 287(1398,123) 288(1383,123) 289(1368,123) 290(1353,123) 291(1338,123) 292(1323,123) 293(1308,123) 294(1293,123) 295(1278,123) 296(1263,123) 297(1248,123) 298(1233,123) 299(1218,123) 300(1203,123) 301(1188,123) 302(1173,123) 303(1158,123) 304(1143,123) 305(1128,123) 306(1113,123) 307(1098,123) 308(1083,123) 309(1068,123) 310(1053,123) 311(1038,123) 312(1023,123) 313(1008,123) 314(993,123) 315(978,123) 316(963,123) 317(948,123) 318(933,123) 319(918,123) 320(903,123) 321(888,123) 322(873,123) 323(858,123) 324(843,123) 325(828,123) 326(813,123) 327(798,123) 328(783,123) 329(768,123) 330(753,123) 331(738,123) 332(723,123) 333(708,123) 334(693,123) 335(678,123) 336(663,123) 337(648,123) 338(633,123) 339(618,123) 340(603,123) 341(588,123) 342(573,123) 343(558,123) 344(543,123) 345(528,123) 346(513,123) 347(498,123) 348(483,123) 349(468,123) 350(453,123) 351(438,123) 352(423,123) 353(408,123) 354(393,123) 355(378,123) 356(363,123) 357(348,123) 358(333,123) 359(318,123) 360(303,123) 361(288,123) 362(273,123) 363(258,123) 364(243,123) 365(228,123) 366(213,123) 367(198,123) 368(183,123) 369(168,123) 370(153,123) 371(138,123) 372(123,123)

## TAPE404-20 [mil]
pads (404):
  oval 75x12 smd: 1(0,0) 2(0,-20) 3(0,-40) 4(0,-60) 5(0,-80) 6(0,-100) 7(0,-120) 8(0,-140) 9(0,-160) 10(0,-180) 11(0,-200) 12(0,-220) 13(0,-240) 14(0,-260) 15(0,-280) 16(0,-300) 17(0,-320) 18(0,-340) 19(0,-360) 20(0,-380) 21(0,-400) 22(0,-420) 23(0,-440) 24(0,-460) 25(0,-480) 26(0,-500) 27(0,-520) 28(0,-540) 29(0,-560) 30(0,-580) 31(0,-600) 32(0,-620) 33(0,-640) 34(0,-660) 35(0,-680) 36(0,-700) 37(0,-720) 38(0,-740) 39(0,-760) 40(0,-780) 41(0,-800) 42(0,-820) 43(0,-840) 44(0,-860) 45(0,-880) 46(0,-900) 47(0,-920) 48(0,-940) 49(0,-960) 50(0,-980) 51(0,-1000) 52(0,-1020) 53(0,-1040) 54(0,-1060) 55(0,-1080) 56(0,-1100) 57(0,-1120) 58(0,-1140) 59(0,-1160) 60(0,-1180) 61(0,-1200) 62(0,-1220) 63(0,-1240) 64(0,-1260) 65(0,-1280) 66(0,-1300) 67(0,-1320) 68(0,-1340) 69(0,-1360) 70(0,-1380) 71(0,-1400) 72(0,-1420) 73(0,-1440) 74(0,-1460) 75(0,-1480) 76(0,-1500) 77(0,-1520) 78(0,-1540) 79(0,-1560) 80(0,-1580) 81(0,-1600) 82(0,-1620) 83(0,-1640) 84(0,-1660) 85(0,-1680) 86(0,-1700) 87(0,-1720) 88(0,-1740) 89(0,-1760) 90(0,-1780) 91(0,-1800) 92(0,-1820) 93(0,-1840) 94(0,-1860) 95(0,-1880) 96(0,-1900) 97(0,-1920) 98(0,-1940) 99(0,-1960) 100(0,-1980) 101(0,-2000) 203(2225,-2000) 204(2225,-1980) 205(2225,-1960) 206(2225,-1940) 207(2225,-1920) 208(2225,-1900) 209(2225,-1880) 210(2225,-1860) 211(2225,-1840) 212(2225,-1820) 213(2225,-1800) 214(2225,-1780) 215(2225,-1760) 216(2225,-1740) 217(2225,-1720) 218(2225,-1700) 219(2225,-1680) 220(2225,-1660) 221(2225,-1640) 222(2225,-1620) 223(2225,-1600) 224(2225,-1580) 225(2225,-1560) 226(2225,-1540) 227(2225,-1520) 228(2225,-1500) 229(2225,-1480) 230(2225,-1460) 231(2225,-1440) 232(2225,-1420) 233(2225,-1400) 234(2225,-1380) 235(2225,-1360) 236(2225,-1340) 237(2225,-1320) 238(2225,-1300) 239(2225,-1280) 240(2225,-1260) 241(2225,-1240) 242(2225,-1220) 243(2225,-1200) 244(2225,-1180) 245(2225,-1160) 246(2225,-1140) 247(2225,-1120) 248(2225,-1100) 249(2225,-1080) 250(2225,-1060) 251(2225,-1040) 252(2225,-1020) 253(2225,-1000) 254(2225,-980) 255(2225,-960) 256(2225,-940) 257(2225,-920) 258(2225,-900) 259(2225,-880) 260(2225,-860) 261(2225,-840) 262(2225,-820) 263(2225,-800) 264(2225,-780) 265(2225,-760) 266(2225,-740) 267(2225,-720) 268(2225,-700) 269(2225,-680) 270(2225,-660) 271(2225,-640) 272(2225,-620) 273(2225,-600) 274(2225,-580) 275(2225,-560) 276(2225,-540) 277(2225,-520) 278(2225,-500) 279(2225,-480) 280(2225,-460) 281(2225,-440) 282(2225,-420) 283(2225,-400) 284(2225,-380) 285(2225,-360) 286(2225,-340) 287(2225,-320) 288(2225,-300) 289(2225,-280) 290(2225,-260) 291(2225,-240) 292(2225,-220) 293(2225,-200) 294(2225,-180) 295(2225,-160) 296(2225,-140) 297(2225,-120) 298(2225,-100) 299(2225,-80) 300(2225,-60) 301(2225,-40) 302(2225,-20) 303(2225,0)
  oval 12x75 smd: 102(113,-2112) 103(133,-2112) 104(153,-2112) 105(173,-2112) 106(193,-2112) 107(213,-2112) 108(233,-2112) 109(253,-2112) 110(273,-2112) 111(293,-2112) 112(313,-2112) 113(333,-2112) 114(353,-2112) 115(373,-2112) 116(393,-2112) 117(413,-2112) 118(433,-2112) 119(453,-2112) 120(473,-2112) 121(493,-2112) 122(513,-2112) 123(533,-2112) 124(553,-2112) 125(573,-2112) 126(593,-2112) 127(613,-2112) 128(633,-2112) 129(653,-2112) 130(673,-2112) 131(693,-2112) 132(713,-2112) 133(733,-2112) 134(753,-2112) 135(773,-2112) 136(793,-2112) 137(813,-2112) 138(833,-2112) 139(853,-2112) 140(873,-2112) 141(893,-2112) 142(913,-2112) 143(933,-2112) 144(953,-2112) 145(973,-2112) 146(993,-2112) 147(1013,-2112) 148(1033,-2112) 149(1053,-2112) 150(1073,-2112) 151(1093,-2112) 152(1113,-2112) 153(1133,-2112) 154(1153,-2112) 155(1173,-2112) 156(1193,-2112) 157(1213,-2112) 158(1233,-2112) 159(1253,-2112) 160(1273,-2112) 161(1293,-2112) 162(1313,-2112) 163(1333,-2112) 164(1353,-2112) 165(1373,-2112) 166(1393,-2112) 167(1413,-2112) 168(1433,-2112) 169(1453,-2112) 170(1473,-2112) 171(1493,-2112) 172(1513,-2112) 173(1533,-2112) 174(1553,-2112) 175(1573,-2112) 176(1593,-2112) 177(1613,-2112) 178(1633,-2112) 179(1653,-2112) 180(1673,-2112) 181(1693,-2112) 182(1713,-2112) 183(1733,-2112) 184(1753,-2112) 185(1773,-2112) 186(1793,-2112) 187(1813,-2112) 188(1833,-2112) 189(1853,-2112) 190(1873,-2112) 191(1893,-2112) 192(1913,-2112) 193(1933,-2112) 194(1953,-2112) 195(1973,-2112) 196(1993,-2112) 197(2013,-2112) 198(2033,-2112) 199(2053,-2112) 200(2073,-2112) 201(2093,-2112) 202(2113,-2112) 304(2113,113) 305(2093,113) 306(2073,113) 307(2053,113) 308(2033,113) 309(2013,113) 310(1993,113) 311(1973,113) 312(1953,113) 313(1933,113) 314(1913,113) 315(1893,113) 316(1873,113) 317(1853,113) 318(1833,113) 319(1813,113) 320(1793,113) 321(1773,113) 322(1753,113) 323(1733,113) 324(1713,113) 325(1693,113) 326(1673,113) 327(1653,113) 328(1633,113) 329(1613,113) 330(1593,113) 331(1573,113) 332(1553,113) 333(1533,113) 334(1513,113) 335(1493,113) 336(1473,113) 337(1453,113) 338(1433,113) 339(1413,113) 340(1393,113) 341(1373,113) 342(1353,113) 343(1333,113) 344(1313,113) 345(1293,113) 346(1273,113) 347(1253,113) 348(1233,113) 349(1213,113) 350(1193,113) 351(1173,113) 352(1153,113) 353(1133,113) 354(1113,113) 355(1093,113) 356(1073,113) 357(1053,113) 358(1033,113) 359(1013,113) 360(993,113) 361(973,113) 362(953,113) 363(933,113) 364(913,113) 365(893,113) 366(873,113) 367(853,113) 368(833,113) 369(813,113) 370(793,113) 371(773,113) 372(753,113) 373(733,113) 374(713,113) 375(693,113) 376(673,113) 377(653,113) 378(633,113) 379(613,113) 380(593,113) 381(573,113) 382(553,113) 383(533,113) 384(513,113) 385(493,113) 386(473,113) 387(453,113) 388(433,113) 389(413,113) 390(393,113) 391(373,113) 392(353,113) 393(333,113) 394(313,113) 395(293,113) 396(273,113) 397(253,113) 398(233,113) 399(213,113) 400(193,113) 401(173,113) 402(153,113) 403(133,113) 404(113,113)

## TAPE428-15 [mil]
pads (428):
  oval 75x8 smd: 1(0,0) 2(0,-15) 3(0,-30) 4(0,-45) 5(0,-60) 6(0,-75) 7(0,-90) 8(0,-105) 9(0,-120) 10(0,-135) 11(0,-150) 12(0,-165) 13(0,-180) 14(0,-195) 15(0,-210) 16(0,-225) 17(0,-240) 18(0,-255) 19(0,-270) 20(0,-285) 21(0,-300) 22(0,-315) 23(0,-330) 24(0,-345) 25(0,-360) 26(0,-375) 27(0,-390) 28(0,-405) 29(0,-420) 30(0,-435) 31(0,-450) 32(0,-465) 33(0,-480) 34(0,-495) 35(0,-510) 36(0,-525) 37(0,-540) 38(0,-555) 39(0,-570) 40(0,-585) 41(0,-600) 42(0,-615) 43(0,-630) 44(0,-645) 45(0,-660) 46(0,-675) 47(0,-690) 48(0,-705) 49(0,-720) 50(0,-735) 51(0,-750) 52(0,-765) 53(0,-780) 54(0,-795) 55(0,-810) 56(0,-825) 57(0,-840) 58(0,-855) 59(0,-870) 60(0,-885) 61(0,-900) 62(0,-915) 63(0,-930) 64(0,-945) 65(0,-960) 66(0,-975) 67(0,-990) 68(0,-1005) 69(0,-1020) 70(0,-1035) 71(0,-1050) 72(0,-1065) 73(0,-1080) 74(0,-1095) 75(0,-1110) 76(0,-1125) 77(0,-1140) 78(0,-1155) 79(0,-1170) 80(0,-1185) 81(0,-1200) 82(0,-1215) 83(0,-1230) 84(0,-1245) 85(0,-1260) 86(0,-1275) 87(0,-1290) 88(0,-1305) 89(0,-1320) 90(0,-1335) 91(0,-1350) 92(0,-1365) 93(0,-1380) 94(0,-1395) 95(0,-1410) 96(0,-1425) 97(0,-1440) 98(0,-1455) 99(0,-1470) 100(0,-1485) 101(0,-1500) 102(0,-1515) 103(0,-1530) 104(0,-1545) 105(0,-1560) 106(0,-1575) 107(0,-1590) 215(1825,-1590) 216(1825,-1575) 217(1825,-1560) 218(1825,-1545) 219(1825,-1530) 220(1825,-1515) 221(1825,-1500) 222(1825,-1485) 223(1825,-1470) 224(1825,-1455) 225(1825,-1440) 226(1825,-1425) 227(1825,-1410) 228(1825,-1395) 229(1825,-1380) 230(1825,-1365) 231(1825,-1350) 232(1825,-1335) 233(1825,-1320) 234(1825,-1305) 235(1825,-1290) 236(1825,-1275) 237(1825,-1260) 238(1825,-1245) 239(1825,-1230) 240(1825,-1215) 241(1825,-1200) 242(1825,-1185) 243(1825,-1170) 244(1825,-1155) 245(1825,-1140) 246(1825,-1125) 247(1825,-1110) 248(1825,-1095) 249(1825,-1080) 250(1825,-1065) 251(1825,-1050) 252(1825,-1035) 253(1825,-1020) 254(1825,-1005) 255(1825,-990) 256(1825,-975) 257(1825,-960) 258(1825,-945) 259(1825,-930) 260(1825,-915) 261(1825,-900) 262(1825,-885) 263(1825,-870) 264(1825,-855) 265(1825,-840) 266(1825,-825) 267(1825,-810) 268(1825,-795) 269(1825,-780) 270(1825,-765) 271(1825,-750) 272(1825,-735) 273(1825,-720) 274(1825,-705) 275(1825,-690) 276(1825,-675) 277(1825,-660) 278(1825,-645) 279(1825,-630) 280(1825,-615) 281(1825,-600) 282(1825,-585) 283(1825,-570) 284(1825,-555) 285(1825,-540) 286(1825,-525) 287(1825,-510) 288(1825,-495) 289(1825,-480) 290(1825,-465) 291(1825,-450) 292(1825,-435) 293(1825,-420) 294(1825,-405) 295(1825,-390) 296(1825,-375) 297(1825,-360) 298(1825,-345) 299(1825,-330) 300(1825,-315) 301(1825,-300) 302(1825,-285) 303(1825,-270) 304(1825,-255) 305(1825,-240) 306(1825,-225) 307(1825,-210) 308(1825,-195) 309(1825,-180) 310(1825,-165) 311(1825,-150) 312(1825,-135) 313(1825,-120) 314(1825,-105) 315(1825,-90) 316(1825,-75) 317(1825,-60) 318(1825,-45) 319(1825,-30) 320(1825,-15) 321(1825,0)
  oval 8x75 smd: 108(118,-1707) 109(133,-1707) 110(148,-1707) 111(163,-1707) 112(178,-1707) 113(193,-1707) 114(208,-1707) 115(223,-1707) 116(238,-1707) 117(253,-1707) 118(268,-1707) 119(283,-1707) 120(298,-1707) 121(313,-1707) 122(328,-1707) 123(343,-1707) 124(358,-1707) 125(373,-1707) 126(388,-1707) 127(403,-1707) 128(418,-1707) 129(433,-1707) 130(448,-1707) 131(463,-1707) 132(478,-1707) 133(493,-1707) 134(508,-1707) 135(523,-1707) 136(538,-1707) 137(553,-1707) 138(568,-1707) 139(583,-1707) 140(598,-1707) 141(613,-1707) 142(628,-1707) 143(643,-1707) 144(658,-1707) 145(673,-1707) 146(688,-1707) 147(703,-1707) 148(718,-1707) 149(733,-1707) 150(748,-1707) 151(763,-1707) 152(778,-1707) 153(793,-1707) 154(808,-1707) 155(823,-1707) 156(838,-1707) 157(853,-1707) 158(868,-1707) 159(883,-1707) 160(898,-1707) 161(913,-1707) 162(928,-1707) 163(943,-1707) 164(958,-1707) 165(973,-1707) 166(988,-1707) 167(1003,-1707) 168(1018,-1707) 169(1033,-1707) 170(1048,-1707) 171(1063,-1707) 172(1078,-1707) 173(1093,-1707) 174(1108,-1707) 175(1123,-1707) 176(1138,-1707) 177(1153,-1707) 178(1168,-1707) 179(1183,-1707) 180(1198,-1707) 181(1213,-1707) 182(1228,-1707) 183(1243,-1707) 184(1258,-1707) 185(1273,-1707) 186(1288,-1707) 187(1303,-1707) 188(1318,-1707) 189(1333,-1707) 190(1348,-1707) 191(1363,-1707) 192(1378,-1707) 193(1393,-1707) 194(1408,-1707) 195(1423,-1707) 196(1438,-1707) 197(1453,-1707) 198(1468,-1707) 199(1483,-1707) 200(1498,-1707) 201(1513,-1707) 202(1528,-1707) 203(1543,-1707) 204(1558,-1707) 205(1573,-1707) 206(1588,-1707) 207(1603,-1707) 208(1618,-1707) 209(1633,-1707) 210(1648,-1707) 211(1663,-1707) 212(1678,-1707) 213(1693,-1707) 214(1708,-1707) 322(1708,118) 323(1693,118) 324(1678,118) 325(1663,118) 326(1648,118) 327(1633,118) 328(1618,118) 329(1603,118) 330(1588,118) 331(1573,118) 332(1558,118) 333(1543,118) 334(1528,118) 335(1513,118) 336(1498,118) 337(1483,118) 338(1468,118) 339(1453,118) 340(1438,118) 341(1423,118) 342(1408,118) 343(1393,118) 344(1378,118) 345(1363,118) 346(1348,118) 347(1333,118) 348(1318,118) 349(1303,118) 350(1288,118) 351(1273,118) 352(1258,118) 353(1243,118) 354(1228,118) 355(1213,118) 356(1198,118) 357(1183,118) 358(1168,118) 359(1153,118) 360(1138,118) 361(1123,118) 362(1108,118) 363(1093,118) 364(1078,118) 365(1063,118) 366(1048,118) 367(1033,118) 368(1018,118) 369(1003,118) 370(988,118) 371(973,118) 372(958,118) 373(943,118) 374(928,118) 375(913,118) 376(898,118) 377(883,118) 378(868,118) 379(853,118) 380(838,118) 381(823,118) 382(808,118) 383(793,118) 384(778,118) 385(763,118) 386(748,118) 387(733,118) 388(718,118) 389(703,118) 390(688,118) 391(673,118) 392(658,118) 393(643,118) 394(628,118) 395(613,118) 396(598,118) 397(583,118) 398(568,118) 399(553,118) 400(538,118) 401(523,118) 402(508,118) 403(493,118) 404(478,118) 405(463,118) 406(448,118) 407(433,118) 408(418,118) 409(403,118) 410(388,118) 411(373,118) 412(358,118) 413(343,118) 414(328,118) 415(313,118) 416(298,118) 417(283,118) 418(268,118) 419(253,118) 420(238,118) 421(223,118) 422(208,118) 423(193,118) 424(178,118) 425(163,118) 426(148,118) 427(133,118) 428(118,118)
